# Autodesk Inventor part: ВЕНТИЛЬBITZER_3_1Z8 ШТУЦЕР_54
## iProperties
Created: 2011-02
Part Number: ВЕНТИЛЬBITZER_3_1Z8 ШТУЦЕР_54
Document SubType Name: Modeling
Designer: Чернышев Юрий
Mass: 65.7826 g
Surface Area: 355.613 cm^2
Volume: 65.7826 cm^3
Density: 1 g/cm^3
Author: Чернышев Юрий
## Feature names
1. ExtrusionBlind1
2. ExtrusionBlind2
3. Hole1
